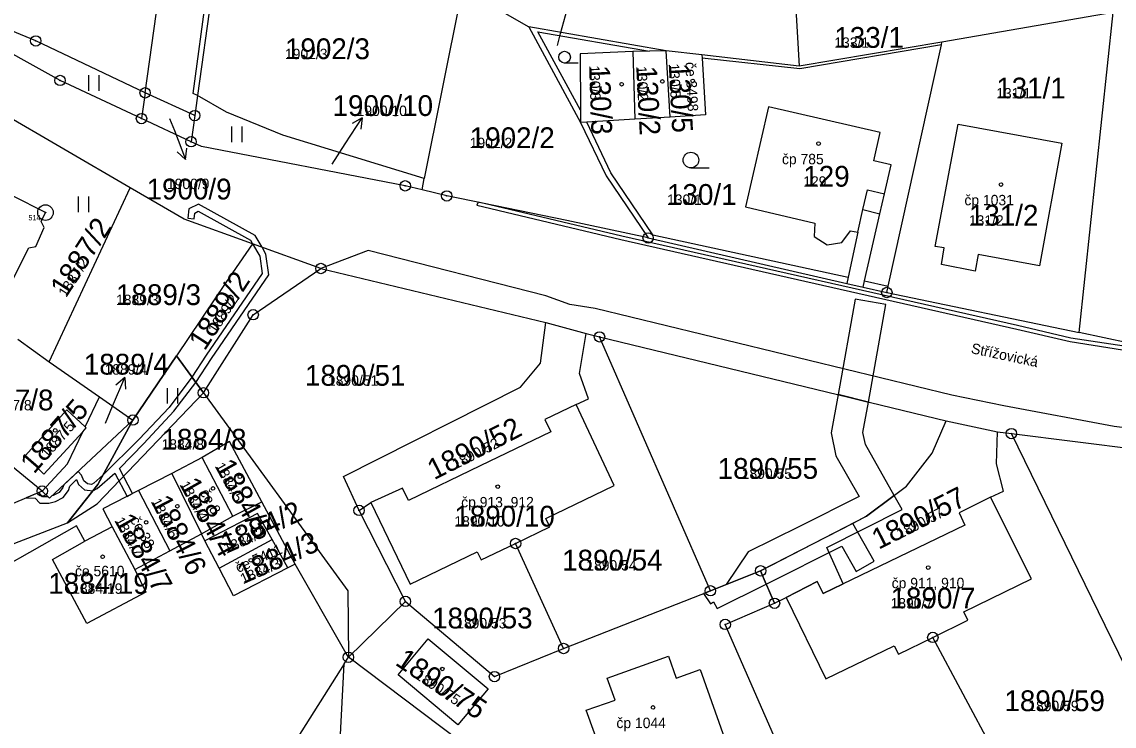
# Model space of a CAD drawing. Extents: x -763628 to -761565, y -976033 to -973833.
# Drawn here: x -762861.1 to -762756, y -974911 to -974843.2 of the extents above; entities that cross this region are included whole.
import ezdxf

# ---------------------------------------------------------------- set-up
doc = ezdxf.new("R2010")
doc.units = 0
for name, color, linetype in [('KN_cisla parcel 1000', 7, 'Continuous'), ('KN_cisla parcel 500', 7, 'Continuous'), ('KN_cisla parcel znacky', 7, 'Continuous'), ('KN_cisla popisna 500', 7, 'Continuous'), ('KN_hranice parcel', 7, 'Continuous'), ('KN_popisy', 7, 'Continuous'), ('KN_vecna bremena', 7, 'Continuous'), ('KN_vnitrni kresba parcel', 7, 'Continuous'), ('KN_znacky bodu BP', 7, 'Continuous'), ('KN_znacky budov', 7, 'Continuous'), ('KN_znacky kultur', 7, 'Continuous')]:
    doc.layers.add(name, color=color, linetype=linetype)

msp = doc.modelspace()

# ---------------------------------------------------------------- linework, layer by layer
at = {"layer": 'KN_cisla parcel znacky'}
for p, q in [((-762809.27, -974844.32), (-762808.49, -974841.42)), ((-762809.57, -974845.48), (-762809.27, -974844.32)), ((-762846.9, -974852.48), (-762846.44, -974853.64)), ((-762830, -974854.93), (-762828.37, -974852.41)), ((-762828.37, -974852.41), (-762829.33, -974852.98)), ((-762828.37, -974852.41), (-762828.49, -974853.53)), ((-762846.44, -974853.64), (-762845.36, -974856.44)), ((-762845.36, -974856.44), (-762845.26, -974855.33)), ((-762831.27, -974856.88), (-762830, -974854.93)), ((-762845.36, -974856.44), (-762846.19, -974855.69)), ((-762852.39, -974880.18), (-762851.22, -974877.42)), ((-762851.22, -974877.42), (-762852.07, -974878.14)), ((-762851.22, -974877.42), (-762851.15, -974878.54)), ((-762853.07, -974881.8), (-762852.39, -974880.18))]:
    msp.add_line(p, q, dxfattribs=at)
at = {"layer": 'KN_hranice parcel'}
for p, q in [((-762849.26, -974850.02), (-762845.45, -974822.7)), ((-762840.4, -974822.89), (-762844.22, -974850.27)), ((-762787.24, -974831.25), (-762786.3, -974847.47)), ((-762818.74, -974839.98), (-762822.41, -974858.26)), ((-762815.54, -974841.83), (-762812.34, -974843.68)), ((-762756.11, -974842.3), (-762772.57, -974845.14)), ((-762759.38, -974873.09), (-762756.11, -974842.3)), ((-762799.12, -974845.99), (-762812.34, -974843.68)), ((-762812.34, -974843.68), (-762807.35, -974852.86)), ((-762802.31, -974846.03), (-762802.13, -974852.55)), ((-762798.74, -974852.35), (-762799.12, -974845.99)), ((-762795.67, -974846.37), (-762799.12, -974845.99)), ((-762772.57, -974845.14), (-762786.3, -974847.47)), ((-762786.3, -974847.47), (-762795.67, -974846.37)), ((-762849.26, -974850.02), (-762849.61, -974852.5)), ((-762844.49, -974852.21), (-762849.26, -974850.02)), ((-762844.22, -974850.27), (-762844.49, -974852.21)), ((-762850.7, -974859.16), (-762865.31, -974850.66)), ((-762844.49, -974852.21), (-762844.84, -974854.73)), ((-762798.74, -974852.35), (-762802.13, -974852.55)), ((-762844.84, -974854.73), (-762849.61, -974852.5)), ((-762822.61, -974859.36), (-762822.41, -974858.26)), ((-762858.5, -974875.89), (-762850.7, -974859.16)), ((-762832.34, -974866.92), (-762838.94, -974864.54)), ((-762800.85, -974863.98), (-762781.72, -974868.35)), ((-762832.34, -974866.92), (-762810.68, -974872.13)), ((-762781.72, -974868.35), (-762780.16, -974868.71)), ((-762780.16, -974868.71), (-762777.88, -974869.23)), ((-762777.88, -974869.23), (-762759.38, -974873.09)), ((-762810.68, -974872.13), (-762806.81, -974873.19)), ((-762806.81, -974873.19), (-762805.53, -974873.5)), ((-762754.57, -974874.12), (-762759.38, -974873.09)), ((-762861.5, -974873.72), (-762858.5, -974875.89)), ((-762805.53, -974873.5), (-762772.16, -974881.58)), ((-762794.86, -974897.93), (-762805.53, -974873.5)), ((-762850.43, -974881.5), (-762846.24, -974875.32)), ((-762846.24, -974875.32), (-762843.65, -974878.88)), ((-762858.5, -974875.89), (-762853.66, -974879.26)), ((-762859.16, -974888.33), (-762870.7, -974878.97)), ((-762855.03, -974882.15), (-762853.66, -974879.26)), ((-762853.66, -974879.26), (-762850.43, -974881.5)), ((-762772.16, -974881.58), (-762767.22, -974882.65)), ((-762767.22, -974882.65), (-762765.89, -974882.81)), ((-762749.04, -974917.33), (-762765.89, -974882.81)), ((-762765.89, -974882.81), (-762729.73, -974887.27)), ((-762843.77, -974885.09), (-762846.69, -974886.66)), ((-762840.82, -974890.74), (-762843.77, -974885.09)), ((-762846.69, -974886.66), (-762849.9, -974888.29)), ((-762846.69, -974886.66), (-762843.84, -974892.46)), ((-762859.16, -974888.33), (-762882, -974898.01)), ((-762849.9, -974888.29), (-762846.89, -974894.08)), ((-762828.67, -974890.2), (-762827.55, -974889.44)), ((-762824.21, -974898.95), (-762828.67, -974890.2)), ((-762843.84, -974892.46), (-762840.82, -974890.74)), ((-762852.43, -974891.77), (-762855.07, -974893.16)), ((-762852.43, -974891.77), (-762850.26, -974895.87)), ((-762846.89, -974894.08), (-762843.84, -974892.46)), ((-762843.5, -974893.11), (-762843.84, -974892.46)), ((-762842.12, -974895.76), (-762843.5, -974893.11)), ((-762842.12, -974895.76), (-762837.04, -974893.01)), ((-762835.52, -974895.73), (-762837.04, -974893.01)), ((-762808.98, -974903.48), (-762813.61, -974893.38)), ((-762850.26, -974895.87), (-762846.89, -974894.08)), ((-762840.74, -974898.4), (-762842.12, -974895.76)), ((-762835.52, -974895.73), (-762840.74, -974898.4)), ((-762794.86, -974897.93), (-762790.02, -974896.01)), ((-762788.69, -974899.13), (-762790.02, -974896.01)), ((-762808.98, -974903.48), (-762794.86, -974897.93)), ((-762788.69, -974899.13), (-762787.55, -974898.56)), ((-762829.7, -974904.33), (-762824.21, -974898.95)), ((-762764.58, -974918.98), (-762773.45, -974902.41)), ((-762830.1, -974904.97), (-762829.7, -974904.33))]:
    msp.add_line(p, q, dxfattribs=at)
for points in [[(-762844.22, -974850.27), (-762844.64, -974850.08), (-762842.02, -974830.57), (-762841.11, -974822.86)], [(-762849.61, -974852.5), (-762857.45, -974848.83), (-762873.22, -974840.05), (-762876.73, -974838.24), (-762879.74, -974836.84)], [(-762849.26, -974850.02), (-762859.79, -974845.03), (-762872.07, -974839.91), (-762879.74, -974836.84)], [(-762802.31, -974846.03), (-762807.4, -974846.27), (-762807.36, -974851.7), (-762807.35, -974852.86)], [(-762799.12, -974845.99), (-762800.73, -974846.01), (-762802.31, -974846.03)], [(-762777.88, -974869.23), (-762777.74, -974868.61), (-762772.63, -974845.41), (-762772.57, -974845.14)], [(-762795.67, -974846.37), (-762795.65, -974846.68), (-762795.33, -974852.15), (-762798.74, -974852.35)], [(-762822.41, -974858.26), (-762836.02, -974854.08), (-762841.44, -974851.89), (-762844.22, -974850.27)], [(-762864.05, -974872.03), (-762860.46, -974864.94), (-762859.77, -974864.8), (-762858.97, -974862.99), (-762859.25, -974862.39), (-762858.85, -974861.54), (-762868.4, -974856.72), (-762865.31, -974850.66)], [(-762780.16, -974868.71), (-762780.02, -974868.11), (-762778.54, -974861.65), (-762778.1, -974859.74), (-762777.46, -974856.96), (-762779.14, -974856.57), (-762778.51, -974853.84), (-762789.26, -974851.36), (-762791.48, -974861), (-762784.82, -974862.55), (-762784.87, -974863.84), (-762783.62, -974864.63), (-762782.2, -974864.43), (-762781.36, -974863.29), (-762780.66, -974863.44), (-762781.59, -974867.77), (-762781.72, -974868.35)], [(-762802.13, -974852.55), (-762806.76, -974852.83), (-762807.35, -974852.86)], [(-762807.35, -974852.86), (-762804.9, -974858.02), (-762800.85, -974863.98)], [(-762769.08, -974865.59), (-762769.39, -974867.17), (-762772.62, -974866.55), (-762772.36, -974864.93), (-762773.22, -974864.79), (-762771.02, -974853.02), (-762761.04, -974854.87), (-762763.2, -974866.67), (-762769.08, -974865.59)], [(-762822.61, -974859.36), (-762824.22, -974858.97), (-762843.85, -974855.19), (-762844.84, -974854.73)], [(-762838.94, -974864.54), (-762845.51, -974862.17), (-762850.7, -974859.16)], [(-762800.85, -974863.98), (-762808.68, -974862.3), (-762820.23, -974859.94), (-762822.61, -974859.36)], [(-762838.94, -974864.54), (-762841.48, -974868.28), (-762846.24, -974875.32)], [(-762843.65, -974878.88), (-762838.86, -974871.37), (-762832.34, -974866.92)], [(-762828.67, -974890.2), (-762830.17, -974886.93), (-762813.13, -974878.35), (-762811.2, -974876.04), (-762810.68, -974872.13)], [(-762807.78, -974880.02), (-762806.6, -974879.46), (-762807.44, -974877.03), (-762806.81, -974873.19)], [(-762843.65, -974878.88), (-762829.74, -974897.94), (-762829.7, -974904.33)], [(-762855.03, -974882.15), (-762856.81, -974880.52), (-762860.82, -974884.96), (-762859.02, -974886.72), (-762855.26, -974882.62)], [(-762807.78, -974880.02), (-762810.78, -974881.45), (-762810.21, -974882.63), (-762817.01, -974885.92), (-762823.91, -974889.24), (-762824.48, -974888.06), (-762827.55, -974889.44)], [(-762813.61, -974893.38), (-762810.3, -974891.79), (-762810.69, -974890.97), (-762804.11, -974887.79), (-762807.78, -974880.02)], [(-762885.56, -974902.53), (-762856.74, -974891.38), (-762853.82, -974887.71), (-762850.43, -974881.5)], [(-762850.43, -974881.5), (-762858.47, -974889.02), (-762859.16, -974888.33)], [(-762790.02, -974896.01), (-762779.84, -974890.76), (-762775.97, -974887.86), (-762773.52, -974884.7), (-762772.16, -974881.58)], [(-762859.16, -974888.33), (-762856.72, -974885.71), (-762855.26, -974882.62)], [(-762855.26, -974882.62), (-762854.92, -974882.25), (-762855.03, -974882.15)], [(-762767.9, -974888.92), (-762766.65, -974888.34), (-762767.31, -974885.72), (-762767.22, -974882.65)], [(-762840.82, -974890.74), (-762838.03, -974889.37), (-762841.14, -974883.56), (-762843.77, -974885.09)], [(-762849.9, -974888.29), (-762853.34, -974890.04), (-762852.43, -974891.77)], [(-762767.9, -974888.92), (-762770.93, -974890.43), (-762770.36, -974891.6), (-762784, -974898.2), (-762784.57, -974897.03), (-762787.55, -974898.56)], [(-762773.45, -974902.41), (-762770.08, -974900.77), (-762770.48, -974899.96), (-762763.94, -974896.78), (-762767.9, -974888.92)], [(-762827.55, -974889.44), (-762823.75, -974897.29), (-762817.3, -974894.17), (-762816.91, -974894.96), (-762813.61, -974893.38)], [(-762837.04, -974893.01), (-762838.45, -974890.48), (-762843.5, -974893.11)], [(-762855.07, -974893.16), (-762855.87, -974891.67), (-762878.29, -974904.39), (-762882.67, -974907.95)], [(-762850.26, -974895.87), (-762849.18, -974898.06), (-762854.87, -974901.09), (-762858.16, -974894.91), (-762855.07, -974893.16)], [(-762829.7, -974904.33), (-762830.04, -974903.74), (-762834.81, -974895.37), (-762835.52, -974895.73)], [(-762787.55, -974898.56), (-762783.74, -974906.4), (-762777.17, -974903.21), (-762776.77, -974904.02), (-762773.45, -974902.41)], [(-762824.21, -974898.95), (-762815.64, -974906.19), (-762808.98, -974903.48)], [(-762781.66, -974928.04), (-762793.43, -974901.16), (-762788.69, -974899.13)], [(-762824.92, -974906), (-762822.02, -974902.56), (-762816.26, -974907.37), (-762819.16, -974910.81), (-762824.92, -974906)], [(-762781.66, -974928.04), (-762789.66, -974930.57), (-762791.18, -974930.15), (-762794.25, -974929.25), (-762815.45, -974915.05), (-762829.7, -974904.33)], [(-762792.96, -974913.65), (-762803.87, -974917.57), (-762806.8, -974909.43), (-762804.03, -974908.44), (-762804.79, -974906.32), (-762798.9, -974904.23), (-762798.15, -974906.35), (-762795.85, -974905.51), (-762792.96, -974913.65)], [(-762830.1, -974904.97), (-762861.69, -974954.95), (-762869.07, -974967.23), (-762888.41, -974938.82)], [(-762837.19, -974987.56), (-762846.73, -974988.55), (-762849.3, -974971.72), (-762864.12, -974971.05), (-762831.34, -974929.04), (-762830.1, -974904.97)]]:
    msp.add_lwpolyline(points, dxfattribs=at)
at = {"layer": 'KN_vecna bremena'}
for points in [[(-762838.01, -974864.88), (-762838.67, -974863.74), (-762844.13, -974860.74), (-762845.04, -974861.19), (-762845.14, -974862.08), (-762844.55, -974862.15), (-762844.48, -974861.59), (-762844.15, -974861.42), (-762839.11, -974864.18), (-762838.94, -974864.54), (-762838.21, -974865.73), (-762837.99, -974867.4), (-762843.37, -974875.25), (-762844.75, -974877.37), (-762844.38, -974877.88), (-762842.87, -974875.59), (-762837.37, -974867.54), (-762837.63, -974865.53)], [(-762780.94, -974869.87), (-762782.57, -974879.06), (-762779.65, -974879.77), (-762777.98, -974870.39)], [(-762843.65, -974878.88), (-762846.24, -974875.32), (-762850.43, -974881.5), (-762853.82, -974887.71), (-762856.74, -974891.38), (-762853.87, -974889.56)], [(-762853.32, -974886.8), (-762853.82, -974887.71), (-762854.3, -974888.32), (-762853.87, -974888.09), (-762852.19, -974886.6), (-762851, -974888.85), (-762850.46, -974888.58), (-762851.73, -974886.17), (-762849.38, -974883.77), (-762846.5, -974880.66), (-762844.38, -974877.88), (-762844.75, -974877.37), (-762846.96, -974880.28), (-762849.82, -974883.35)], [(-762793.35, -974897.33), (-762790.02, -974896.01), (-762779.84, -974890.76), (-762777.16, -974888.75), (-762779.94, -974883.86), (-762780.18, -974882.7), (-762779.65, -974879.77), (-762782.57, -974879.06), (-762783.24, -974882.74), (-762782.78, -974884.94), (-762780.55, -974888.85), (-762786.28, -974891.73), (-762791.21, -974894.18)], [(-762860.72, -974888.99), (-762859.84, -974889.01), (-762859.4, -974889.49), (-762858.53, -974889.49), (-762857.88, -974889.33), (-762857.14, -974888.95), (-762856.63, -974888.28), (-762856.5, -974887.87), (-762855.86, -974887.21), (-762855.67, -974887.7), (-762855.08, -974888.21), (-762854.3, -974888.32), (-762853.82, -974887.71), (-762853.32, -974886.8), (-762854.21, -974887.59), (-762854.41, -974887.69), (-762854.82, -974887.63), (-762855.17, -974887.34), (-762855.37, -974886.82), (-762855.71, -974886.44), (-762857.09, -974887.73), (-762857.17, -974888), (-762857.54, -974888.47), (-762858.1, -974888.77), (-762858.24, -974888.8), (-762858.47, -974889.02), (-762858.6, -974888.89), (-762859.14, -974888.89), (-762859.5, -974888.47)], [(-762777.16, -974888.75), (-762779.84, -974890.76), (-762781.16, -974891.44), (-762790.02, -974896.01), (-762789.48, -974897.28), (-762788.69, -974899.13), (-762787.55, -974898.56), (-762784.57, -974897.03), (-762784, -974898.2), (-762782.08, -974897.27), (-762783.65, -974893.77), (-762776.39, -974890.12)], [(-762790.02, -974896.01), (-762789.48, -974897.28), (-762788.69, -974899.13), (-762787.55, -974898.56), (-762784.57, -974897.03), (-762784, -974898.2), (-762782.08, -974897.27), (-762783.65, -974893.77), (-762776.39, -974890.12), (-762777.16, -974888.75), (-762779.84, -974890.76), (-762781.16, -974891.44)], [(-762790.02, -974896.01), (-762789.48, -974897.28), (-762782.21, -974893.65), (-762780.82, -974896.07), (-762779.09, -974895.08), (-762781.16, -974891.44)], [(-762795.52, -974898.19), (-762794.86, -974899.18), (-762794.55, -974899), (-762794.2, -974899.63), (-762789.48, -974897.28), (-762790.02, -974896.01), (-762794.86, -974897.93)]]:
    msp.add_lwpolyline(points, close=True, dxfattribs=at)
msp.add_lwpolyline([(-762754.41, -974874.5), (-762760.17, -974873.62), (-762765.29, -974872.42), (-762803.39, -974863.8), (-762816.09, -974860.79), (-762817.22, -974860.55), (-762817.35, -974860.84), (-762803.47, -974864.14), (-762765.37, -974872.76), (-762760.23, -974873.96), (-762754.39, -974874.86)], dxfattribs=at)
at = {"layer": 'KN_vnitrni kresba parcel'}
for p, q in [((-762811.46, -974844.16), (-762800.73, -974846.01)), ((-762807.36, -974851.7), (-762811.46, -974844.16)), ((-762772.63, -974845.41), (-762786.26, -974847.72)), ((-762786.26, -974847.72), (-762795.65, -974846.68)), ((-762804.45, -974857.71), (-762806.76, -974852.83)), ((-762800.4, -974863.67), (-762804.45, -974857.71)), ((-762780.19, -974861.26), (-762779.75, -974859.36)), ((-762779.75, -974859.36), (-762778.1, -974859.74)), ((-762780.66, -974863.44), (-762780.19, -974861.26)), ((-762780.19, -974861.26), (-762778.54, -974861.65)), ((-762800.4, -974863.67), (-762781.59, -974867.77)), ((-762827.78, -974865.18), (-762832.34, -974866.92)), ((-762810.71, -974869.55), (-762827.78, -974865.18)), ((-762780.02, -974868.11), (-762777.74, -974868.61)), ((-762808.4, -974870.37), (-762810.71, -974869.55)), ((-762805.94, -974870.77), (-762808.4, -974870.37)), ((-762771.62, -974879.1), (-762805.94, -974870.77)), ((-762766.63, -974880.15), (-762771.62, -974879.1)), ((-762756.01, -974882.11), (-762766.63, -974880.15)), ((-762740.75, -974883.97), (-762756.01, -974882.11)), ((-762834.81, -974895.37), (-762838.03, -974889.37))]:
    msp.add_line(p, q, dxfattribs=at)
at = {"layer": 'KN_znacky bodu BP'}
for centre, radius in [((-762859.79, -974845.03), 0.5), ((-762859.79, -974845.03), 0.0303), ((-762857.45, -974848.83), 0.5), ((-762857.45, -974848.83), 0.0303), ((-762849.26, -974850.02), 0.5), ((-762849.26, -974850.02), 0.0303), ((-762849.61, -974852.5), 0.5), ((-762844.49, -974852.21), 0.5), ((-762844.49, -974852.21), 0.0303), ((-762849.61, -974852.5), 0.0303), ((-762844.84, -974854.73), 0.5), ((-762844.84, -974854.73), 0.0303), ((-762824.22, -974858.97), 0.5), ((-762824.22, -974858.97), 0.0303), ((-762820.23, -974859.94), 0.5), ((-762858.85, -974861.54), 0.75), ((-762820.23, -974859.94), 0.0303), ((-762858.85, -974861.54), 0.03), ((-762800.85, -974863.98), 0.5), ((-762800.85, -974863.98), 0.0303), ((-762832.34, -974866.92), 0.5), ((-762832.34, -974866.92), 0.0303), ((-762777.88, -974869.23), 0.5), ((-762777.88, -974869.23), 0.0303), ((-762838.86, -974871.37), 0.5), ((-762838.86, -974871.37), 0.0303), ((-762805.53, -974873.5), 0.5), ((-762805.53, -974873.5), 0.0303), ((-762843.65, -974878.88), 0.5), ((-762843.65, -974878.88), 0.0303), ((-762850.43, -974881.5), 0.5), ((-762850.43, -974881.5), 0.0303), ((-762765.89, -974882.81), 0.5), ((-762765.89, -974882.81), 0.0303), ((-762859.16, -974888.33), 0.5), ((-762859.16, -974888.33), 0.0303), ((-762828.67, -974890.2), 0.5), ((-762828.67, -974890.2), 0.0303), ((-762813.61, -974893.38), 0.5), ((-762813.61, -974893.38), 0.0303), ((-762790.02, -974896.01), 0.5), ((-762790.02, -974896.01), 0.0303), ((-762794.86, -974897.93), 0.5), ((-762824.21, -974898.95), 0.5), ((-762794.86, -974897.93), 0.0303), ((-762788.69, -974899.13), 0.5), ((-762824.21, -974898.95), 0.0303), ((-762788.69, -974899.13), 0.0303), ((-762793.43, -974901.16), 0.5), ((-762793.43, -974901.16), 0.0303), ((-762773.45, -974902.41), 0.5), ((-762773.45, -974902.41), 0.0303), ((-762829.7, -974904.33), 0.5), ((-762808.98, -974903.48), 0.5), ((-762808.98, -974903.48), 0.0303), ((-762829.7, -974904.33), 0.0303), ((-762815.64, -974906.19), 0.5), ((-762815.64, -974906.19), 0.0303)]:
    msp.add_circle(centre, radius, dxfattribs=at)
at = {"layer": 'KN_znacky budov'}
for centre in [(-762803.4, -974849.19), (-762799.48, -974848.92), (-762796.56, -974848.87), (-762784.45, -974854.9), (-762766.89, -974858.85), (-762857.91, -974882.5), (-762840.14, -974886.96), (-762842.73, -974888.08), (-762815.32, -974887.91), (-762846.16, -974889.79), (-762849.16, -974891.34), (-762840.3, -974891.94), (-762853.35, -974894.66), (-762839.09, -974894.99), (-762773.89, -974895.69), (-762820.66, -974905.45), (-762800.38, -974909.15)]:
    msp.add_circle(centre, 0.175, dxfattribs=at)
at = {"layer": 'KN_znacky kultur'}
for p, q in [((-762808.9, -974847.15), (-762807.58, -974847.15)), ((-762854.67, -974849.82), (-762854.67, -974848.32)), ((-762853.67, -974849.82), (-762853.67, -974848.32)), ((-762840.93, -974854.76), (-762840.93, -974853.26)), ((-762839.93, -974854.76), (-762839.93, -974853.26)), ((-762796.73, -974857.24), (-762794.98, -974857.24)), ((-762855.67, -974861.49), (-762855.67, -974859.99)), ((-762854.67, -974861.49), (-762854.67, -974859.99)), ((-762847.1, -974879.92), (-762847.1, -974878.42)), ((-762846.1, -974879.92), (-762846.1, -974878.42))]:
    msp.add_line(p, q, dxfattribs=at)
for centre, radius in [((-762808.89, -974846.59), 0.562), ((-762796.73, -974856.49), 0.75)]:
    msp.add_circle(centre, radius, dxfattribs=at)

# ---------------------------------------------------------------- texts
at = {"layer": 'KN_cisla parcel 1000'}
for s, p in [('133/1', (-762782.93, -974845.69)), ('1902/3', (-762835.8, -974846.78)), ('131/1', (-762767.35, -974850.56)), ('1900/10', (-762831.22, -974852.25)), ('1902/2', (-762818.02, -974855.34)), ('129', (-762785.92, -974859.05)), ('1900/9', (-762849.12, -974860.28)), ('130/1', (-762799.03, -974860.8)), ('131/2', (-762769.98, -974862.8)), ('1889/3', (-762852.06, -974870.44)), ('1889/4', (-762855.16, -974877.13)), ('1890/51', (-762833.87, -974878.2)), ('1887/8', (-762866.26, -974880.57)), ('1884/8', (-762847.68, -974884.35)), ('1890/55', (-762794.16, -974887.16)), ('1890/10', (-762819.5, -974891.75)), ('1890/54', (-762809.13, -974895.98)), ('1884/19', (-762858.58, -974898.22)), ('1890/7', (-762777.52, -974899.63)), ('1890/53', (-762821.64, -974901.55)), ('1890/59', (-762766.56, -974909.51))]:
    msp.add_text(s, height=2, dxfattribs=at).set_placement(p)
for s, rotation, p in [('130/3', 272, (-762806.53, -974847.4)), ('130/2', 273, (-762802, -974847.48)), ('130/5', 273, (-762798.87, -974847.23)), ('1887/2', 57, (-762856.85, -974869.76)), ('1889/2', 57, (-762843.53, -974874.92)), ('1887/5', 49, (-762859.95, -974886.76)), ('1890/52', 27, (-762821.44, -974887.3)), ('1884/5', 299, (-762842.59, -974885.93)), ('1884/4', 299, (-762845.98, -974887.71)), ('1890/57', 27, (-762778.67, -974894)), ('1884/6', 297, (-762848.73, -974889.34)), ('1884/2', 24, (-762841.43, -974894.37)), ('1884/7', 299, (-762852.25, -974891.17)), ('1884/3', 24, (-762839.83, -974897.31)), ('1890/75', 326, (-762825.29, -974904.99))]:
    msp.add_text(s, height=2, rotation=rotation, dxfattribs=at).set_placement(p)
at = {"layer": 'KN_cisla parcel 500'}
for s, p in [('133/1', (-762782.93, -974845.69)), ('1902/3', (-762835.8, -974846.78)), ('131/1', (-762767.35, -974850.56)), ('1900/10', (-762828.9, -974852.25)), ('1902/2', (-762818.02, -974855.34)), ('1900/9', (-762847.16, -974859.28)), ('129', (-762785.92, -974859.05)), ('130/1', (-762799.03, -974860.8)), ('131/2', (-762769.98, -974862.8)), ('1889/3', (-762852.06, -974870.44)), ('1889/4', (-762853.16, -974877.13)), ('1890/51', (-762831.66, -974878.2)), ('1887/8', (-762864.27, -974880.57)), ('1884/8', (-762847.68, -974884.35)), ('1890/55', (-762791.84, -974887.16)), ('1890/10', (-762819.5, -974891.75)), ('1890/54', (-762806.8, -974895.98)), ('1884/19', (-762856.28, -974898.22)), ('1890/7', (-762777.52, -974899.63)), ('1890/53', (-762819.32, -974901.55)), ('1890/59', (-762764.26, -974909.51))]:
    msp.add_text(s, height=1, dxfattribs=at).set_placement(p)
for s, rotation, p in [('130/3', 272, (-762806.53, -974847.4)), ('130/2', 273, (-762802, -974847.48)), ('130/5', 273, (-762798.87, -974847.23)), ('1887/2', 57, (-762856.85, -974869.76)), ('1889/2', 57, (-762842.45, -974873.26)), ('1887/5', 49, (-762858.65, -974885.26)), ('1890/52', 27, (-762819.37, -974886.25)), ('1884/5', 299, (-762842.59, -974885.93)), ('1884/4', 299, (-762845.98, -974887.71)), ('1884/6', 297, (-762848.73, -974889.34)), ('1890/57', 27, (-762776.61, -974892.95)), ('1884/7', 299, (-762852.25, -974891.17)), ('1884/2', 24, (-762841.43, -974894.37)), ('1884/3', 24, (-762839.83, -974897.31)), ('1890/75', 326, (-762823.37, -974906.28))]:
    msp.add_text(s, height=1, rotation=rotation, dxfattribs=at).set_placement(p)
at = {"layer": 'KN_cisla popisna 500'}
for s, rotation, p in [('če 3498', 273, (-762797.27, -974847.08)), ('če 8', 299, (-762844.02, -974888.47)), ('če 38', 299, (-762850.73, -974891.11)), ('če 5411', 24, (-762840.3, -974896.22))]:
    msp.add_text(s, height=1, rotation=rotation, dxfattribs=at).set_placement(p)
for s, p in [('čp 785', (-762787.97, -974856.89)), ('čp 1031', (-762770.41, -974860.84)), ('čp 913, 912', (-762818.84, -974889.9)), ('če 5610', (-762856.01, -974896.53)), ('čp 911, 910', (-762777.41, -974897.68)), ('čp 1044', (-762803.9, -974911.14))]:
    msp.add_text(s, height=1, dxfattribs=at).set_placement(p)
at = {"layer": 'KN_popisy'}
msp.add_text('Střížovická', height=1, rotation=348, dxfattribs=at).set_placement((-762769.83, -974875.06))
at = {"layer": 'KN_znacky bodu BP'}
msp.add_text('514', height=0.5, dxfattribs=at).set_placement((-762860.49, -974862.29))

doc.saveas('drawing.dxf')
